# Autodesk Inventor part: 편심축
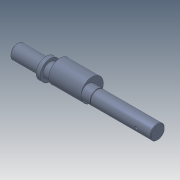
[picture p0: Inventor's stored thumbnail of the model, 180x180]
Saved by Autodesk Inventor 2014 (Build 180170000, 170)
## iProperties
Manager: 한국ATC센터
Company: 한국ATC센터
Created: 2014-10
Part Number: 편심축
Document SubType Name: Modeling
Designer: 한국ATC센터
Density: 7.86 g/cm^3
Material: 강, 연강
Mass: 1459.29 g
Surface Area: 294.403 cm^2
Volume: 185.661 cm^3
Appearance: 강철
Author: KYOUNG IL JANG
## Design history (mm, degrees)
sketch "스케치1"
  geometry: L1 (-147, 0)-(147, 0); L2 (-147, 0)-(-147, 12.5); L3 (-147, 12.5)-(-47, 12.5); L4 (-47, 12.5)-(-47, 17.5); L5 (-47, 17.5)-(-40, 17.5); L6 (-40, 17.5)-(-40, 12.5); L7 (-40, 12.5)-(41.65, 12.5); L8 (41.65, 12.5)-(41.65, 11.95); L9 (41.65, 11.95)-(43, 11.95); L10 (43, 11.95)-(43, 12.5); L11 (43, 12.5)-(147, 12.5); L12 (147, 12.5)-(147, 0); L13 (114, 12.5)-(114, 9.1); L14 (114, 9.1)-(139, 9.1); L15 (139, 9.1)-(139, 12.5); L16 (122, -12.5)-(124.5, -12.5); L17 (124.5, -12.5)-(122, -10); L18 (122, -10)-(122, -12.5); L19 (-114, 12.5)-(-114, 9.1); L20 (-114, 9.1)-(-139, 9.1); L21 (-139, 9.1)-(-139, 12.5); L22 (-122, -12.5)-(-122, -10); L23 (-122, -10)-(-119.5, -12.5); L24 (-119.5, -12.5)-(-122, -12.5); 2 further points
  constraints: 48 end point, 11 parallel, 8 perpendicular, 5 collinear, 4 point on line, 1 coincident, 1 horizontal, 1 midpoint, 1 vertical
  dimensions: "d0" = 294 distance of L1.start L1.end (derived); "d1" = 25 diameter of L3 L1; "d2" = 35 diameter of L5 L1; "d3" = 100 distance of L2.end L3.end; "d4" = 187 distance between parallel lines of L12 L6; "d6" = 1.35 distance of L8.end L9.end; "d7" = 23.9 diameter of L9 L1; "d8" = 3.4 distance between parallel lines of L14 L11; "d9" = 8 distance between parallel lines of L15 L12; "d10" = 25 distance of L13.end L14.end; "d11" = 25 diameter of L16 L1 (= d1); "d12" = 25 distance from line of L12 L16.start; "d13" = 45 deg angle of L17 L18; "d14" = 5 diameter of L16.end L18; "d27" = 104 distance between parallel lines of L10 L12; "d32" = 7 distance of L4.end L5.end; "d33" = 8 distance between parallel lines of L2 L21; "d34" = 25 distance between parallel lines of L21 L19; "d35" = 3.4 distance between parallel lines of L3 L20; "d36" = 25 distance from line of L22.start L2; "d37" = 5 diameter of L23.end L22
revolve "회전1" stored, may be unused: angle "d15" = 90 deg
revolve "회전2" stored, may be unused: angle "d16" = 90 deg
revolve "회전3" stored, may be unused: angle "d38" = 90 deg
extrude "돌출1" cut sketch "스케치1" stored distance "d17" = 8; taper "d18" = 0 deg
fillet "모깎기1" dims "d19" = 4
node "작업 평면1"
sketch "스케치2"
  geometry: C1 r 12.5 at (0, 0) reference; C2 r 19.5 at (0, 7); 1 further point
  constraints: 1 centre point, 1 tangent, 1 vertical alignment
  dimensions: "d21" = 7 distance of point (0, 0) C2.centre; "d30" = 39 diameter of C2 (derived)
extrude "돌출2" join sketch "스케치2" distance "d22" = 56; taper "d23" = 0 deg
chamfer "모따기1" distance "d24" = 1; stored, may be unused: second distance "d25" = 2, angle "d26" = 45 deg
node "솔리드1"
